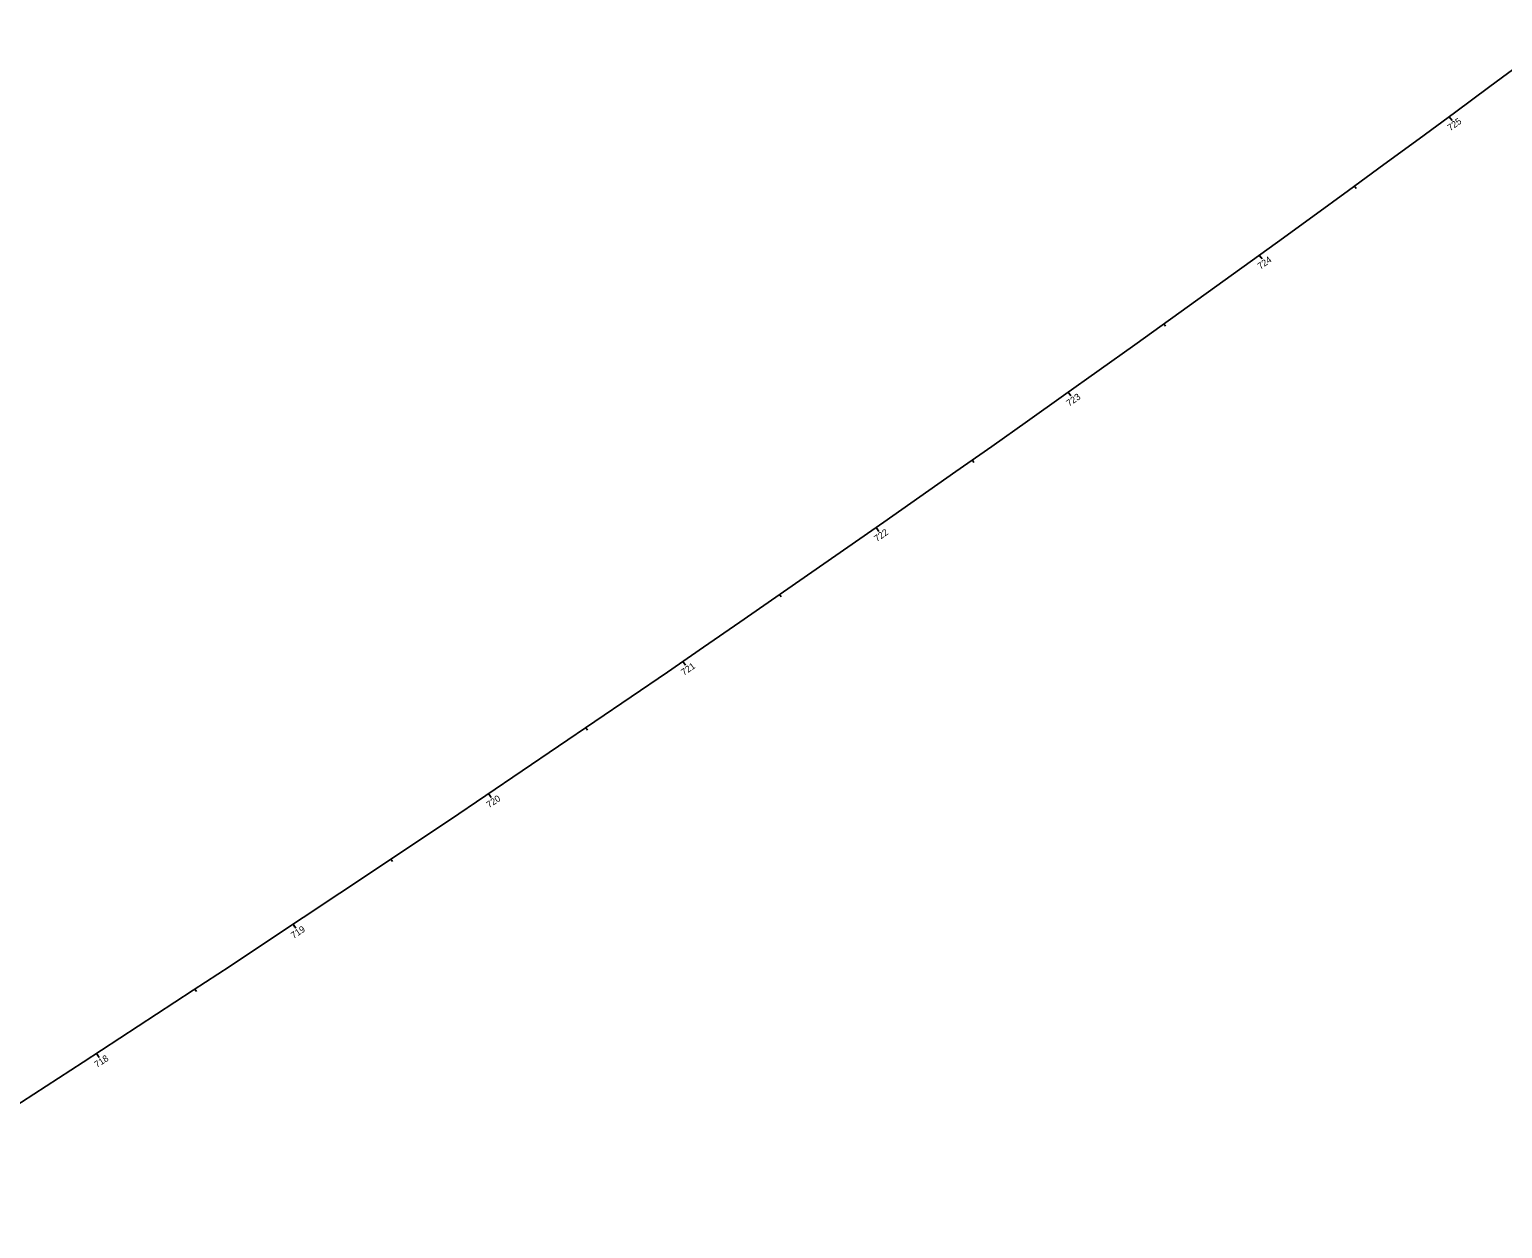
# Model space of a CAD drawing. Extents: x 1492452 to 1496782, y 514026 to 517659.
# Drawn here: x 1493100 to 1493726, y 514419 to 514929 of the extents above; entities that cross this region are included whole.
import ezdxf

# ---------------------------------------------------------------- set-up
doc = ezdxf.new("R2010")
doc.units = 0
for name, color, linetype in [('Default', 7, 'Continuous'), ('DT_X_TIN_Hull', 7, 'Continuous'), ('GE_X_Cells', 7, 'Continuous'), ('UT_X_Water_Cells', 7, 'Continuous'), ('VG_X_Cells', 7, 'Continuous')]:
    doc.layers.add(name, color=color, linetype=linetype)

msp = doc.modelspace()

# ---------------------------------------------------------------- linework, layer by layer
at = {"layer": 'Default'}
msp.add_arc((1486425.91, 524780.42), 12277.67, 302.444021, 313.600151, dxfattribs=at)
at = {"layer": 'DT_X_TIN_Hull'}
for p, q in [((1493703.67, 514892.28), (1493704.86, 514890.67)), ((1493663.35, 514862.72), (1493664.05, 514861.75)), ((1493622.9, 514833.33), (1493624.07, 514831.71)), ((1493582.33, 514804.1), (1493583.03, 514803.13)), ((1493541.64, 514775.04), (1493542.8, 514773.41)), ((1493500.84, 514746.15), (1493501.53, 514745.17)), ((1493459.91, 514717.42), (1493461.06, 514715.78)), ((1493418.87, 514688.86), (1493419.56, 514687.87)), ((1493377.72, 514660.46), (1493378.85, 514658.81)), ((1493336.45, 514632.24), (1493337.12, 514631.24)), ((1493295.06, 514604.18), (1493296.18, 514602.52)), ((1493253.56, 514576.29), (1493254.23, 514575.29)), ((1493211.95, 514548.57), (1493213.06, 514546.9)), ((1493170.23, 514521.02), (1493170.89, 514520.01)), ((1493128.39, 514493.64), (1493129.48, 514491.96))]:
    msp.add_line(p, q, dxfattribs=at)
at = {"layer": 'GE_X_Cells'}
msp.add_arc((1486425.91, 524780.42), 12277.67, 302.444021, 313.600151, dxfattribs=at)
at = {"layer": 'UT_X_Water_Cells'}
for p, q in [((1493703.67, 514892.28), (1493704.86, 514890.67)), ((1493622.9, 514833.33), (1493623.6, 514832.36)), ((1493541.64, 514775.04), (1493542.34, 514774.07)), ((1493459.91, 514717.42), (1493460.6, 514716.44)), ((1493377.72, 514660.46), (1493378.4, 514659.47)), ((1493295.06, 514604.18), (1493296.18, 514602.52)), ((1493211.95, 514548.57), (1493212.62, 514547.57)), ((1493128.39, 514493.64), (1493129.05, 514492.63))]:
    msp.add_line(p, q, dxfattribs=at)
at = {"layer": 'VG_X_Cells'}
for p, q in [((1493703.67, 514892.28), (1493704.39, 514891.31)), ((1493295.06, 514604.18), (1493296.18, 514602.52))]:
    msp.add_line(p, q, dxfattribs=at)

# ---------------------------------------------------------------- texts
at = {"layer": 'DT_X_TIN_Hull'}
for s, rotation, p in [('725', 36.35343, (1493704.16, 514886.06)), ('724', 35.88676, (1493623.38, 514827.14)), ('723', 35.42009, (1493542.05, 514768.83)), ('722', 34.95343, (1493460.27, 514711.2)), ('721', 34.48676, (1493378.16, 514654.33)), ('720', 34.02009, (1493295.31, 514597.95)), ('719', 33.55343, (1493212.17, 514542.35)), ('718', 33.08676, (1493128.54, 514487.41))]:
    msp.add_text(s, height=2.8, rotation=rotation, dxfattribs=at).set_placement(p)
at = {"layer": 'UT_X_Water_Cells'}
for s, rotation, p in [('725', 36.35343, (1493704.16, 514886.06)), ('720', 34.02009, (1493295.31, 514597.95))]:
    msp.add_text(s, height=2.8, rotation=rotation, dxfattribs=at).set_placement(p)
at = {"layer": 'VG_X_Cells'}
msp.add_text('720', height=2.8, rotation=34.02009, dxfattribs=at).set_placement((1493295.31, 514597.95))

doc.saveas('drawing.dxf')
